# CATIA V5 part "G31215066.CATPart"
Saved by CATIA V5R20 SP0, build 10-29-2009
Part number: G31215066
Revision: 5
Definition: design
Nomenclature: G31215066
Source: made
Description: NOT SPECIFIED
Bounding box of the stored display mesh (mm): x -6 to 66, y -12.31 to 12.31, z -12.5 to 12.5
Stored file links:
  C:\Users\Raffaele\Desktop\3D X SITO CF\BOLEX\23-BUSH REF 312\G31215066.CATPart

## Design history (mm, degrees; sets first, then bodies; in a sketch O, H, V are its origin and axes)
Body1 "MANIFOLD_SOLID_BREP #14731" (main body)
  Solid1: solid without history
Body2 "MANIFOLD_SOLID_BREP #14874"
  Solid2: solid without history
Body3 "MANIFOLD_SOLID_BREP #15017"
  Solid3: solid without history
Body4 "MANIFOLD_SOLID_BREP #15160"
  Solid4: solid without history
Body5 "MANIFOLD_SOLID_BREP #15303"
  Solid5: solid without history
Body6 "MANIFOLD_SOLID_BREP #15448"
  Solid6: solid without history
Body7 "MANIFOLD_SOLID_BREP #15593"
  Solid7: solid without history
Body8 "MANIFOLD_SOLID_BREP #15738"
  Solid8: solid without history
Body9 "MANIFOLD_SOLID_BREP #15883"
  Solid9: solid without history
Body10 "MANIFOLD_SOLID_BREP #16028"
  Solid10: solid without history
Body11 "MANIFOLD_SOLID_BREP #16173"
  Solid11: solid without history
Body12 "MANIFOLD_SOLID_BREP #16318"
  Solid12: solid without history
Body13 "MANIFOLD_SOLID_BREP #16463"
  Solid13: solid without history
Body14 "MANIFOLD_SOLID_BREP #16608"
  Solid14: solid without history
Body15 "MANIFOLD_SOLID_BREP #16753"
  Solid15: solid without history
Body16 "MANIFOLD_SOLID_BREP #16898"
  Solid16: solid without history
Body17 "MANIFOLD_SOLID_BREP #17043"
  Solid17: solid without history
Body18 "MANIFOLD_SOLID_BREP #17188"
  Solid18: solid without history
Body19 "MANIFOLD_SOLID_BREP #17333"
  Solid19: solid without history
Body20 "MANIFOLD_SOLID_BREP #17479"
  Solid20: solid without history
Body21 "MANIFOLD_SOLID_BREP #17624"
  Solid21: solid without history
Body22 "MANIFOLD_SOLID_BREP #17769"
  Solid22: solid without history
Body23 "MANIFOLD_SOLID_BREP #17915"
  Solid23: solid without history
Body24 "MANIFOLD_SOLID_BREP #18060"
  Solid24: solid without history
Body25 "MANIFOLD_SOLID_BREP #18205"
  Solid25: solid without history
Body26 "MANIFOLD_SOLID_BREP #18350"
  Solid26: solid without history
Body27 "MANIFOLD_SOLID_BREP #18495"
  Solid27: solid without history
Body28 "MANIFOLD_SOLID_BREP #18640"
  Solid28: solid without history
Body29 "MANIFOLD_SOLID_BREP #18785"
  Solid29: solid without history
Body30 "MANIFOLD_SOLID_BREP #18930"
  Solid30: solid without history
Body31 "MANIFOLD_SOLID_BREP #19075"
  Solid31: solid without history
Body32 "MANIFOLD_SOLID_BREP #19218"
  Solid32: solid without history
Body33 "MANIFOLD_SOLID_BREP #19361"
  Solid33: solid without history
Body34 "MANIFOLD_SOLID_BREP #19506"
  Solid34: solid without history
Body35 "MANIFOLD_SOLID_BREP #19651"
  Solid35: solid without history
Body36 "MANIFOLD_SOLID_BREP #19797"
  Solid36: solid without history
Body37 "MANIFOLD_SOLID_BREP #19942"
  Solid37: solid without history
Body38 "MANIFOLD_SOLID_BREP #20087"
  Solid38: solid without history
Body39 "MANIFOLD_SOLID_BREP #20233"
  Solid39: solid without history
Body40 "MANIFOLD_SOLID_BREP #20378"
  Solid40: solid without history
Body41 "MANIFOLD_SOLID_BREP #20523"
  Solid41: solid without history
Body42 "MANIFOLD_SOLID_BREP #20668"
  Solid42: solid without history
Body43 "MANIFOLD_SOLID_BREP #20813"
  Solid43: solid without history
Body44 "MANIFOLD_SOLID_BREP #20958"
  Solid44: solid without history
Body45 "MANIFOLD_SOLID_BREP #21103"
  Solid45: solid without history
Body46 "MANIFOLD_SOLID_BREP #21248"
  Solid46: solid without history
Body47 "MANIFOLD_SOLID_BREP #21393"
  Solid47: solid without history
Body48 "MANIFOLD_SOLID_BREP #21538"
  Solid48: solid without history
Body49 "MANIFOLD_SOLID_BREP #21683"
  Solid49: solid without history
Body50 "MANIFOLD_SOLID_BREP #21829"
  Solid50: solid without history
Body51 "MANIFOLD_SOLID_BREP #21974"
  Solid51: solid without history
Body52 "MANIFOLD_SOLID_BREP #22119"
  Solid52: solid without history
Body53 "MANIFOLD_SOLID_BREP #22265"
  Solid53: solid without history
Body54 "MANIFOLD_SOLID_BREP #22410"
  Solid54: solid without history
Body55 "MANIFOLD_SOLID_BREP #22555"
  Solid55: solid without history
Body56 "MANIFOLD_SOLID_BREP #22698"
  Solid56: solid without history
Body57 "MANIFOLD_SOLID_BREP #22841"
  Solid57: solid without history
Body58 "MANIFOLD_SOLID_BREP #22986"
  Solid58: solid without history
Body59 "MANIFOLD_SOLID_BREP #23131"
  Solid59: solid without history
Body60 "MANIFOLD_SOLID_BREP #23276"
  Solid60: solid without history
Body61 "MANIFOLD_SOLID_BREP #23421"
  Solid61: solid without history
Body62 "MANIFOLD_SOLID_BREP #23566"
  Solid62: solid without history
Body63 "MANIFOLD_SOLID_BREP #23711"
  Solid63: solid without history
Body64 "MANIFOLD_SOLID_BREP #23854"
  Solid64: solid without history
Body65 "MANIFOLD_SOLID_BREP #23997"
  Solid65: solid without history
Body66 "MANIFOLD_SOLID_BREP #24142"
  Solid66: solid without history
Body67 "MANIFOLD_SOLID_BREP #24287"
  Solid67: solid without history
Body68 "MANIFOLD_SOLID_BREP #24433"
  Solid68: solid without history
Body69 "MANIFOLD_SOLID_BREP #24578"
  Solid69: solid without history
Body70 "MANIFOLD_SOLID_BREP #24723"
  Solid70: solid without history
Body71 "MANIFOLD_SOLID_BREP #24869"
  Solid71: solid without history
Body72 "MANIFOLD_SOLID_BREP #25014"
  Solid72: solid without history
Body73 "MANIFOLD_SOLID_BREP #25159"
  Solid73: solid without history
Body74 "MANIFOLD_SOLID_BREP #25304"
  Solid74: solid without history
Body75 "MANIFOLD_SOLID_BREP #25449"
  Solid75: solid without history
Body76 "MANIFOLD_SOLID_BREP #25594"
  Solid76: solid without history
Body77 "MANIFOLD_SOLID_BREP #25739"
  Solid77: solid without history
Body78 "MANIFOLD_SOLID_BREP #25884"
  Solid78: solid without history
Body79 "MANIFOLD_SOLID_BREP #26029"
  Solid79: solid without history
Body80 "MANIFOLD_SOLID_BREP #26174"
  Solid80: solid without history
Body81 "MANIFOLD_SOLID_BREP #26319"
  Solid81: solid without history
Body82 "MANIFOLD_SOLID_BREP #26465"
  Solid82: solid without history
Body83 "MANIFOLD_SOLID_BREP #26610"
  Solid83: solid without history
Body84 "MANIFOLD_SOLID_BREP #26755"
  Solid84: solid without history
Body85 "MANIFOLD_SOLID_BREP #26901"
  Solid85: solid without history
Body86 "MANIFOLD_SOLID_BREP #27046"
  Solid86: solid without history
Body87 "MANIFOLD_SOLID_BREP #27191"
  Solid87: solid without history
Body88 "MANIFOLD_SOLID_BREP #27334"
  Solid88: solid without history
Body89 "MANIFOLD_SOLID_BREP #27477"
  Solid89: solid without history
Body90 "MANIFOLD_SOLID_BREP #27622"
  Solid90: solid without history
Body91 "MANIFOLD_SOLID_BREP #27767"
  Solid91: solid without history
Body92 "MANIFOLD_SOLID_BREP #27912"
  Solid92: solid without history
Body93 "MANIFOLD_SOLID_BREP #28057"
  Solid93: solid without history
Body94 "MANIFOLD_SOLID_BREP #28202"
  Solid94: solid without history
Body95 "MANIFOLD_SOLID_BREP #28347"
  Solid95: solid without history
Body96 "MANIFOLD_SOLID_BREP #28490"
  Solid96: solid without history
Body97 "MANIFOLD_SOLID_BREP #28633"
  Solid97: solid without history
Body98 "MANIFOLD_SOLID_BREP #28778"
  Solid98: solid without history
Body99 "MANIFOLD_SOLID_BREP #28923"
  Solid99: solid without history
Body100 "MANIFOLD_SOLID_BREP #29069"
  Solid100: solid without history
Body101 "MANIFOLD_SOLID_BREP #29214"
  Solid101: solid without history
Body102 "MANIFOLD_SOLID_BREP #29359"
  Solid102: solid without history
Body103 "MANIFOLD_SOLID_BREP #29505"
  Solid103: solid without history
Body104 "MANIFOLD_SOLID_BREP #29650"
  Solid104: solid without history
Body105 "MANIFOLD_SOLID_BREP #29795"
  Solid105: solid without history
